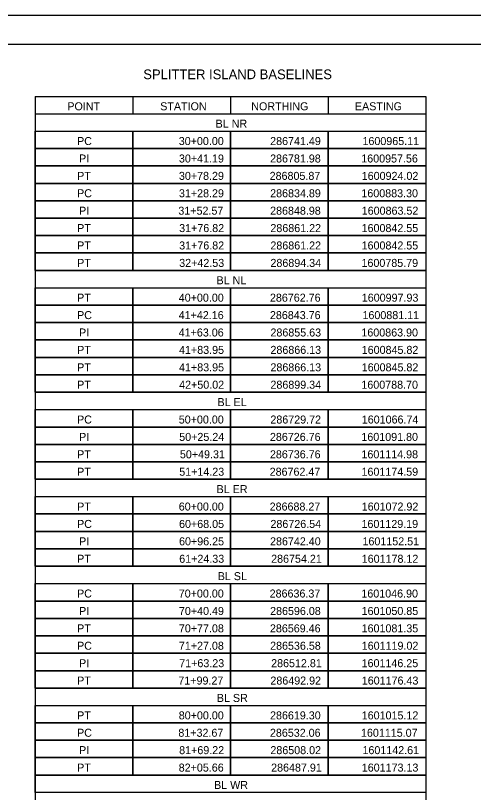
# Model space of a CAD drawing. Extents: x 0 to 34, y 0 to 22.
# Drawn here: x 17 to 25, y 8.41 to 22 of the extents above; entities that cross this region are included whole.
import ezdxf

# ---------------------------------------------------------------- set-up
doc = ezdxf.new("R2010")
doc.units = 0
for name, color, linetype in [('SH_Border', 7, 'Continuous'), ('SH_Cut_Line', 7, 'Continuous'), ('SH_Text', 7, 'Continuous')]:
    doc.layers.add(name, color=color, linetype=linetype)

msp = doc.modelspace()

# ---------------------------------------------------------------- linework, layer by layer
at = {"layer": 'SH_Border'}
msp.add_lwpolyline([(1.5, 21.5), (33.5, 21.5), (33.5, 0.5), (1.5, 0.5)], close=True, dxfattribs=at)
at = {"layer": 'SH_Cut_Line'}
msp.add_lwpolyline([(0, 0), (34, 0), (34, 22), (0, 22)], close=True, dxfattribs=at)
at = {"layer": 'SH_Text'}
for p, q in [((17.338, 20.587), (24.169, 20.587)), ((17.338, 20.587), (17.338, 19.674)), ((19.046, 20.587), (19.046, 20.283)), ((20.754, 20.587), (20.754, 20.283)), ((22.461, 20.587), (22.461, 20.283)), ((24.169, 20.587), (24.169, 19.674)), ((17.338, 20.283), (24.169, 20.283)), ((17.338, 19.978), (24.169, 19.978)), ((19.046, 19.978), (19.046, 19.674)), ((20.754, 19.978), (20.754, 19.674)), ((22.461, 19.978), (22.461, 19.674)), ((17.338, 19.674), (24.169, 19.674)), ((17.338, 19.674), (17.338, 19.37)), ((19.046, 19.674), (19.046, 19.37)), ((20.754, 19.674), (20.754, 19.37)), ((22.461, 19.674), (22.461, 19.37)), ((24.169, 19.674), (24.169, 19.37)), ((17.338, 19.37), (24.169, 19.37)), ((17.338, 19.37), (17.338, 18.761)), ((19.046, 19.37), (19.046, 18.761)), ((20.754, 19.37), (20.754, 18.761)), ((22.461, 19.37), (22.461, 18.761)), ((24.169, 19.37), (24.169, 18.761)), ((17.338, 19.065), (24.169, 19.065)), ((17.338, 18.761), (24.169, 18.761)), ((17.338, 18.761), (17.338, 18.457)), ((19.046, 18.761), (19.046, 18.457)), ((20.754, 18.761), (20.754, 18.457)), ((22.461, 18.761), (22.461, 18.457)), ((24.169, 18.761), (24.169, 18.457)), ((17.338, 18.457), (24.169, 18.457)), ((17.338, 18.457), (17.338, 16.63)), ((19.046, 18.457), (19.046, 17.543)), ((20.754, 18.457), (20.754, 17.543)), ((22.461, 18.457), (22.461, 17.543)), ((24.169, 18.457), (24.169, 16.63)), ((17.338, 18.152), (24.169, 18.152)), ((17.338, 17.848), (24.169, 17.848)), ((17.338, 17.543), (24.169, 17.543)), ((17.338, 17.239), (24.169, 17.239)), ((19.046, 17.239), (19.046, 16.63)), ((20.754, 17.239), (20.754, 16.63)), ((22.461, 17.239), (22.461, 16.63)), ((17.338, 16.935), (24.169, 16.935)), ((17.338, 16.63), (24.169, 16.63)), ((17.338, 16.63), (17.338, 16.326)), ((19.046, 16.63), (19.046, 16.326)), ((20.754, 16.63), (20.754, 16.326)), ((22.461, 16.63), (22.461, 16.326)), ((24.169, 16.63), (24.169, 16.326)), ((17.338, 16.326), (24.169, 16.326)), ((17.338, 16.326), (17.338, 14.804)), ((19.046, 16.326), (19.046, 15.413)), ((20.754, 16.326), (20.754, 15.413)), ((22.461, 16.326), (22.461, 15.413)), ((24.169, 16.326), (24.169, 14.804)), ((17.338, 16.022), (24.169, 16.022)), ((17.338, 15.717), (24.169, 15.717)), ((17.338, 15.413), (24.169, 15.413)), ((17.338, 15.109), (24.169, 15.109)), ((19.046, 15.109), (19.046, 14.804)), ((20.754, 15.109), (20.754, 14.804)), ((22.461, 15.109), (22.461, 14.804)), ((17.338, 14.804), (24.169, 14.804)), ((17.338, 14.804), (17.338, 14.5)), ((19.046, 14.804), (19.046, 14.5)), ((20.754, 14.804), (20.754, 14.5)), ((22.461, 14.804), (22.461, 14.5)), ((24.169, 14.804), (24.169, 14.5)), ((17.338, 14.5), (24.169, 14.5)), ((17.338, 14.5), (17.338, 12.978)), ((19.046, 14.5), (19.046, 13.891)), ((20.754, 14.5), (20.754, 13.891)), ((22.461, 14.5), (22.461, 13.891)), ((24.169, 14.5), (24.169, 12.978)), ((17.338, 14.196), (24.169, 14.196)), ((17.338, 13.891), (24.169, 13.891)), ((17.338, 13.587), (24.169, 13.587)), ((19.046, 13.587), (19.046, 12.978)), ((20.754, 13.587), (20.754, 12.978)), ((22.461, 13.587), (22.461, 12.978)), ((17.338, 13.283), (24.169, 13.283)), ((17.338, 12.978), (24.169, 12.978)), ((17.338, 12.978), (17.338, 12.674)), ((19.046, 12.978), (19.046, 12.674)), ((20.754, 12.978), (20.754, 12.674)), ((22.461, 12.978), (22.461, 12.674)), ((24.169, 12.978), (24.169, 12.674)), ((17.338, 12.674), (24.169, 12.674)), ((17.338, 12.674), (17.338, 11.761)), ((19.046, 12.674), (19.046, 12.37)), ((20.754, 12.674), (20.754, 12.37)), ((22.461, 12.674), (22.461, 12.37)), ((24.169, 12.674), (24.169, 11.761)), ((17.338, 12.37), (24.169, 12.37)), ((17.338, 12.065), (24.169, 12.065)), ((19.046, 12.065), (19.046, 11.761)), ((20.754, 12.065), (20.754, 11.761)), ((22.461, 12.065), (22.461, 11.761)), ((17.338, 11.761), (24.169, 11.761)), ((17.338, 11.761), (17.338, 11.457)), ((19.046, 11.761), (19.046, 11.457)), ((20.754, 11.761), (20.754, 11.457)), ((22.461, 11.761), (22.461, 11.457)), ((24.169, 11.761), (24.169, 11.457)), ((17.338, 11.457), (24.169, 11.457)), ((17.338, 11.457), (17.338, 10.848)), ((19.046, 11.457), (19.046, 10.848)), ((20.754, 11.457), (20.754, 10.848)), ((22.461, 11.457), (22.461, 10.848)), ((24.169, 11.457), (24.169, 10.848)), ((17.338, 11.152), (24.169, 11.152)), ((17.338, 10.848), (24.169, 10.848)), ((17.338, 10.848), (17.338, 10.543)), ((19.046, 10.848), (19.046, 10.543)), ((20.754, 10.848), (20.754, 10.543)), ((22.461, 10.848), (22.461, 10.543)), ((24.169, 10.848), (24.169, 10.543)), ((17.338, 10.543), (24.169, 10.543)), ((17.338, 10.543), (17.338, 9.326)), ((19.046, 10.543), (19.046, 10.239)), ((20.754, 10.543), (20.754, 10.239)), ((22.461, 10.543), (22.461, 10.239)), ((24.169, 10.543), (24.169, 9.326)), ((17.338, 10.239), (24.169, 10.239)), ((17.338, 9.935), (24.169, 9.935)), ((19.046, 9.935), (19.046, 9.326)), ((20.754, 9.935), (20.754, 9.326)), ((22.461, 9.935), (22.461, 9.326)), ((17.338, 9.63), (24.169, 9.63)), ((17.338, 9.326), (24.169, 9.326)), ((17.338, 9.326), (17.338, 9.022)), ((19.046, 9.326), (19.046, 9.022)), ((20.754, 9.326), (20.754, 9.022)), ((22.461, 9.326), (22.461, 9.022)), ((24.169, 9.326), (24.169, 9.022)), ((17.338, 9.022), (24.169, 9.022)), ((17.338, 9.022), (17.338, 8.109)), ((19.046, 9.022), (19.046, 8.717)), ((20.754, 9.022), (20.754, 8.717)), ((22.461, 9.022), (22.461, 8.717)), ((24.169, 9.022), (24.169, 8.109)), ((17.338, 8.717), (24.169, 8.717))]:
    msp.add_line(p, q, dxfattribs=at)
for points in [[(17.338, 19.978), (19.046, 19.978), (19.046, 19.674), (17.338, 19.674)], [(19.046, 19.978), (20.754, 19.978), (20.754, 19.674), (19.046, 19.674)], [(20.754, 19.978), (22.461, 19.978), (22.461, 19.674), (20.754, 19.674)], [(22.461, 19.978), (24.169, 19.978), (24.169, 19.674), (22.461, 19.674)], [(17.338, 19.674), (19.046, 19.674), (19.046, 19.37), (17.338, 19.37)], [(19.046, 19.674), (20.754, 19.674), (20.754, 19.37), (19.046, 19.37)], [(20.754, 19.674), (22.461, 19.674), (22.461, 19.37), (20.754, 19.37)], [(22.461, 19.674), (24.169, 19.674), (24.169, 19.37), (22.461, 19.37)], [(17.338, 19.37), (19.046, 19.37), (19.046, 19.065), (17.338, 19.065)], [(19.046, 19.37), (20.754, 19.37), (20.754, 19.065), (19.046, 19.065)], [(20.754, 19.37), (22.461, 19.37), (22.461, 19.065), (20.754, 19.065)], [(22.461, 19.37), (24.169, 19.37), (24.169, 19.065), (22.461, 19.065)], [(17.338, 19.065), (19.046, 19.065), (19.046, 18.761), (17.338, 18.761)], [(19.046, 19.065), (20.754, 19.065), (20.754, 18.761), (19.046, 18.761)], [(20.754, 19.065), (22.461, 19.065), (22.461, 18.761), (20.754, 18.761)], [(22.461, 19.065), (24.169, 19.065), (24.169, 18.761), (22.461, 18.761)], [(17.338, 18.761), (19.046, 18.761), (19.046, 18.457), (17.338, 18.457)], [(19.046, 18.761), (20.754, 18.761), (20.754, 18.457), (19.046, 18.457)], [(20.754, 18.761), (22.461, 18.761), (22.461, 18.457), (20.754, 18.457)], [(22.461, 18.761), (24.169, 18.761), (24.169, 18.457), (22.461, 18.457)], [(17.338, 18.457), (19.046, 18.457), (19.046, 18.152), (17.338, 18.152)], [(19.046, 18.457), (20.754, 18.457), (20.754, 18.152), (19.046, 18.152)], [(20.754, 18.457), (22.461, 18.457), (22.461, 18.152), (20.754, 18.152)], [(22.461, 18.457), (24.169, 18.457), (24.169, 18.152), (22.461, 18.152)], [(17.338, 18.152), (19.046, 18.152), (19.046, 17.848), (17.338, 17.848)], [(19.046, 18.152), (20.754, 18.152), (20.754, 17.848), (19.046, 17.848)], [(20.754, 18.152), (22.461, 18.152), (22.461, 17.848), (20.754, 17.848)], [(22.461, 18.152), (24.169, 18.152), (24.169, 17.848), (22.461, 17.848)], [(17.338, 17.848), (19.046, 17.848), (19.046, 17.543), (17.338, 17.543)], [(19.046, 17.848), (20.754, 17.848), (20.754, 17.543), (19.046, 17.543)], [(20.754, 17.848), (22.461, 17.848), (22.461, 17.543), (20.754, 17.543)], [(22.461, 17.848), (24.169, 17.848), (24.169, 17.543), (22.461, 17.543)], [(17.338, 17.239), (19.046, 17.239), (19.046, 16.935), (17.338, 16.935)], [(19.046, 17.239), (20.754, 17.239), (20.754, 16.935), (19.046, 16.935)], [(20.754, 17.239), (22.461, 17.239), (22.461, 16.935), (20.754, 16.935)], [(22.461, 17.239), (24.169, 17.239), (24.169, 16.935), (22.461, 16.935)], [(17.338, 16.935), (19.046, 16.935), (19.046, 16.63), (17.338, 16.63)], [(19.046, 16.935), (20.754, 16.935), (20.754, 16.63), (19.046, 16.63)], [(20.754, 16.935), (22.461, 16.935), (22.461, 16.63), (20.754, 16.63)], [(22.461, 16.935), (24.169, 16.935), (24.169, 16.63), (22.461, 16.63)], [(17.338, 16.63), (19.046, 16.63), (19.046, 16.326), (17.338, 16.326)], [(19.046, 16.63), (20.754, 16.63), (20.754, 16.326), (19.046, 16.326)], [(20.754, 16.63), (22.461, 16.63), (22.461, 16.326), (20.754, 16.326)], [(22.461, 16.63), (24.169, 16.63), (24.169, 16.326), (22.461, 16.326)], [(17.338, 16.326), (19.046, 16.326), (19.046, 16.022), (17.338, 16.022)], [(19.046, 16.326), (20.754, 16.326), (20.754, 16.022), (19.046, 16.022)], [(20.754, 16.326), (22.461, 16.326), (22.461, 16.022), (20.754, 16.022)], [(22.461, 16.326), (24.169, 16.326), (24.169, 16.022), (22.461, 16.022)], [(17.338, 16.022), (19.046, 16.022), (19.046, 15.717), (17.338, 15.717)], [(19.046, 16.022), (20.754, 16.022), (20.754, 15.717), (19.046, 15.717)], [(20.754, 16.022), (22.461, 16.022), (22.461, 15.717), (20.754, 15.717)], [(22.461, 16.022), (24.169, 16.022), (24.169, 15.717), (22.461, 15.717)], [(17.338, 15.717), (19.046, 15.717), (19.046, 15.413), (17.338, 15.413)], [(19.046, 15.717), (20.754, 15.717), (20.754, 15.413), (19.046, 15.413)], [(20.754, 15.717), (22.461, 15.717), (22.461, 15.413), (20.754, 15.413)], [(22.461, 15.717), (24.169, 15.717), (24.169, 15.413), (22.461, 15.413)], [(17.338, 15.109), (19.046, 15.109), (19.046, 14.804), (17.338, 14.804)], [(19.046, 15.109), (20.754, 15.109), (20.754, 14.804), (19.046, 14.804)], [(20.754, 15.109), (22.461, 15.109), (22.461, 14.804), (20.754, 14.804)], [(22.461, 15.109), (24.169, 15.109), (24.169, 14.804), (22.461, 14.804)], [(17.338, 14.804), (19.046, 14.804), (19.046, 14.5), (17.338, 14.5)], [(19.046, 14.804), (20.754, 14.804), (20.754, 14.5), (19.046, 14.5)], [(20.754, 14.804), (22.461, 14.804), (22.461, 14.5), (20.754, 14.5)], [(22.461, 14.804), (24.169, 14.804), (24.169, 14.5), (22.461, 14.5)], [(17.338, 14.5), (19.046, 14.5), (19.046, 14.196), (17.338, 14.196)], [(19.046, 14.5), (20.754, 14.5), (20.754, 14.196), (19.046, 14.196)], [(20.754, 14.5), (22.461, 14.5), (22.461, 14.196), (20.754, 14.196)], [(22.461, 14.5), (24.169, 14.5), (24.169, 14.196), (22.461, 14.196)], [(17.338, 14.196), (19.046, 14.196), (19.046, 13.891), (17.338, 13.891)], [(19.046, 14.196), (20.754, 14.196), (20.754, 13.891), (19.046, 13.891)], [(20.754, 14.196), (22.461, 14.196), (22.461, 13.891), (20.754, 13.891)], [(22.461, 14.196), (24.169, 14.196), (24.169, 13.891), (22.461, 13.891)], [(17.338, 13.587), (19.046, 13.587), (19.046, 13.283), (17.338, 13.283)], [(19.046, 13.587), (20.754, 13.587), (20.754, 13.283), (19.046, 13.283)], [(20.754, 13.587), (22.461, 13.587), (22.461, 13.283), (20.754, 13.283)], [(22.461, 13.587), (24.169, 13.587), (24.169, 13.283), (22.461, 13.283)], [(17.338, 13.283), (19.046, 13.283), (19.046, 12.978), (17.338, 12.978)], [(19.046, 13.283), (20.754, 13.283), (20.754, 12.978), (19.046, 12.978)], [(20.754, 13.283), (22.461, 13.283), (22.461, 12.978), (20.754, 12.978)], [(22.461, 13.283), (24.169, 13.283), (24.169, 12.978), (22.461, 12.978)], [(17.338, 12.978), (19.046, 12.978), (19.046, 12.674), (17.338, 12.674)], [(19.046, 12.978), (20.754, 12.978), (20.754, 12.674), (19.046, 12.674)], [(20.754, 12.978), (22.461, 12.978), (22.461, 12.674), (20.754, 12.674)], [(22.461, 12.978), (24.169, 12.978), (24.169, 12.674), (22.461, 12.674)], [(17.338, 12.674), (19.046, 12.674), (19.046, 12.37), (17.338, 12.37)], [(19.046, 12.674), (20.754, 12.674), (20.754, 12.37), (19.046, 12.37)], [(20.754, 12.674), (22.461, 12.674), (22.461, 12.37), (20.754, 12.37)], [(22.461, 12.674), (24.169, 12.674), (24.169, 12.37), (22.461, 12.37)], [(17.338, 12.065), (19.046, 12.065), (19.046, 11.761), (17.338, 11.761)], [(19.046, 12.065), (20.754, 12.065), (20.754, 11.761), (19.046, 11.761)], [(20.754, 12.065), (22.461, 12.065), (22.461, 11.761), (20.754, 11.761)], [(22.461, 12.065), (24.169, 12.065), (24.169, 11.761), (22.461, 11.761)], [(17.338, 11.761), (19.046, 11.761), (19.046, 11.457), (17.338, 11.457)], [(19.046, 11.761), (20.754, 11.761), (20.754, 11.457), (19.046, 11.457)], [(20.754, 11.761), (22.461, 11.761), (22.461, 11.457), (20.754, 11.457)], [(22.461, 11.761), (24.169, 11.761), (24.169, 11.457), (22.461, 11.457)], [(17.338, 11.457), (19.046, 11.457), (19.046, 11.152), (17.338, 11.152)], [(19.046, 11.457), (20.754, 11.457), (20.754, 11.152), (19.046, 11.152)], [(20.754, 11.457), (22.461, 11.457), (22.461, 11.152), (20.754, 11.152)], [(22.461, 11.457), (24.169, 11.457), (24.169, 11.152), (22.461, 11.152)], [(17.338, 11.152), (19.046, 11.152), (19.046, 10.848), (17.338, 10.848)], [(19.046, 11.152), (20.754, 11.152), (20.754, 10.848), (19.046, 10.848)], [(20.754, 11.152), (22.461, 11.152), (22.461, 10.848), (20.754, 10.848)], [(22.461, 11.152), (24.169, 11.152), (24.169, 10.848), (22.461, 10.848)], [(17.338, 10.848), (19.046, 10.848), (19.046, 10.543), (17.338, 10.543)], [(19.046, 10.848), (20.754, 10.848), (20.754, 10.543), (19.046, 10.543)], [(20.754, 10.848), (22.461, 10.848), (22.461, 10.543), (20.754, 10.543)], [(22.461, 10.848), (24.169, 10.848), (24.169, 10.543), (22.461, 10.543)], [(17.338, 10.543), (19.046, 10.543), (19.046, 10.239), (17.338, 10.239)], [(19.046, 10.543), (20.754, 10.543), (20.754, 10.239), (19.046, 10.239)], [(20.754, 10.543), (22.461, 10.543), (22.461, 10.239), (20.754, 10.239)], [(22.461, 10.543), (24.169, 10.543), (24.169, 10.239), (22.461, 10.239)], [(17.338, 9.935), (19.046, 9.935), (19.046, 9.63), (17.338, 9.63)], [(19.046, 9.935), (20.754, 9.935), (20.754, 9.63), (19.046, 9.63)], [(20.754, 9.935), (22.461, 9.935), (22.461, 9.63), (20.754, 9.63)], [(22.461, 9.935), (24.169, 9.935), (24.169, 9.63), (22.461, 9.63)], [(17.338, 9.63), (19.046, 9.63), (19.046, 9.326), (17.338, 9.326)], [(19.046, 9.63), (20.754, 9.63), (20.754, 9.326), (19.046, 9.326)], [(20.754, 9.63), (22.461, 9.63), (22.461, 9.326), (20.754, 9.326)], [(22.461, 9.63), (24.169, 9.63), (24.169, 9.326), (22.461, 9.326)], [(17.338, 9.326), (19.046, 9.326), (19.046, 9.022), (17.338, 9.022)], [(19.046, 9.326), (20.754, 9.326), (20.754, 9.022), (19.046, 9.022)], [(20.754, 9.326), (22.461, 9.326), (22.461, 9.022), (20.754, 9.022)], [(22.461, 9.326), (24.169, 9.326), (24.169, 9.022), (22.461, 9.022)], [(17.338, 9.022), (19.046, 9.022), (19.046, 8.717), (17.338, 8.717)], [(19.046, 9.022), (20.754, 9.022), (20.754, 8.717), (19.046, 8.717)], [(20.754, 9.022), (22.461, 9.022), (22.461, 8.717), (20.754, 8.717)], [(22.461, 9.022), (24.169, 9.022), (24.169, 8.717), (22.461, 8.717)], [(17.338, 8.717), (24.169, 8.717), (24.169, 8.413), (17.338, 8.413)]]:
    msp.add_lwpolyline(points, close=True, dxfattribs=at)

# ---------------------------------------------------------------- texts
for s, height, p in [('SPLITTER ISLAND BASELINES', 0.17, (19.23, 20.887)), ('POINT', 0.14, (17.903, 20.343)), ('STATION', 0.14, (19.526, 20.343)), ('NORTHING', 0.14, (21.117, 20.343)), ('EASTING', 0.14, (22.928, 20.343)), ('BL NR', 0.14, (20.494, 20.039)), ('PC', 0.14, (18.073, 19.735)), ('30+00.00', 0.14, (19.85, 19.735)), ('286741.49', 0.14, (21.447, 19.735)), ('1600965.11', 0.14, (23.06, 19.735)), ('PI', 0.14, (18.108, 19.43)), ('30+41.19', 0.14, (19.853, 19.43)), ('286781.98', 0.14, (21.446, 19.43)), ('1600957.56', 0.14, (23.039, 19.43)), ('PT', 0.14, (18.074, 19.126)), ('30+78.29', 0.14, (19.853, 19.126)), ('286805.87', 0.14, (21.438, 19.126)), ('1600924.02', 0.14, (23.047, 19.126)), ('PC', 0.14, (18.073, 18.822)), ('31+28.29', 0.14, (19.853, 18.822)), ('286834.89', 0.14, (21.447, 18.822)), ('1600883.30', 0.14, (23.041, 18.822)), ('PI', 0.14, (18.108, 18.517)), ('31+52.57', 0.14, (19.843, 18.517)), ('286848.98', 0.14, (21.446, 18.517)), ('1600863.52', 0.14, (23.047, 18.517)), ('PT', 0.14, (18.074, 18.213)), ('31+76.82', 0.14, (19.857, 18.213)), ('286861.22', 0.14, (21.451, 18.213)), ('1600842.55', 0.14, (23.045, 18.213)), ('PT', 0.14, (18.074, 17.909)), ('31+76.82', 0.14, (19.857, 17.909)), ('286861.22', 0.14, (21.451, 17.909)), ('1600842.55', 0.14, (23.045, 17.909)), ('PT', 0.14, (18.074, 17.604)), ('32+42.53', 0.14, (19.858, 17.604)), ('286894.34', 0.14, (21.452, 17.604)), ('1600785.79', 0.14, (23.043, 17.604)), ('BL NL', 0.14, (20.51, 17.3)), ('PT', 0.14, (18.074, 16.996)), ('40+00.00', 0.14, (19.85, 16.996)), ('286762.76', 0.14, (21.443, 16.996)), ('1600997.93', 0.14, (23.048, 16.996)), ('PC', 0.14, (18.073, 16.691)), ('41+42.16', 0.14, (19.849, 16.691)), ('286843.76', 0.14, (21.443, 16.691)), ('1600881.11', 0.14, (23.06, 16.691)), ('PI', 0.14, (18.108, 16.387)), ('41+63.06', 0.14, (19.849, 16.387)), ('286855.63', 0.14, (21.452, 16.387)), ('1600863.90', 0.14, (23.041, 16.387)), ('PT', 0.14, (18.074, 16.083)), ('41+83.95', 0.14, (19.855, 16.083)), ('286866.13', 0.14, (21.452, 16.083)), ('1600845.82', 0.14, (23.047, 16.083)), ('PT', 0.14, (18.074, 15.778)), ('41+83.95', 0.14, (19.855, 15.778)), ('286866.13', 0.14, (21.452, 15.778)), ('1600845.82', 0.14, (23.047, 15.778)), ('PT', 0.14, (18.074, 15.474)), ('42+50.02', 0.14, (19.857, 15.474)), ('286899.34', 0.14, (21.452, 15.474)), ('1600788.70', 0.14, (23.041, 15.474)), ('BL EL', 0.14, (20.527, 15.17)), ('PC', 0.14, (18.073, 14.865)), ('50+00.00', 0.14, (19.85, 14.865)), ('286729.72', 0.14, (21.451, 14.865)), ('1601066.74', 0.14, (23.048, 14.865)), ('PI', 0.14, (18.108, 14.561)), ('50+25.24', 0.14, (19.858, 14.561)), ('286726.76', 0.14, (21.443, 14.561)), ('1601091.80', 0.14, (23.041, 14.561)), ('PT', 0.14, (18.074, 14.257)), ('50+49.31', 0.14, (19.87, 14.257)), ('286736.76', 0.14, (21.443, 14.257)), ('1601114.98', 0.14, (23.042, 14.257)), ('PT', 0.14, (18.074, 13.952)), ('51+14.23', 0.14, (19.858, 13.952)), ('286762.47', 0.14, (21.438, 13.952)), ('1601174.59', 0.14, (23.043, 13.952)), ('BL ER', 0.14, (20.511, 13.648)), ('PT', 0.14, (18.074, 13.343)), ('60+00.00', 0.14, (19.85, 13.343)), ('286688.27', 0.14, (21.438, 13.343)), ('1601072.92', 0.14, (23.047, 13.343)), ('PC', 0.14, (18.073, 13.039)), ('60+68.05', 0.14, (19.855, 13.039)), ('286726.54', 0.14, (21.452, 13.039)), ('1601129.19', 0.14, (23.043, 13.039)), ('PI', 0.14, (18.108, 12.735)), ('60+96.25', 0.14, (19.855, 12.735)), ('286742.40', 0.14, (21.445, 12.735)), ('1601152.51', 0.14, (23.06, 12.735)), ('PT', 0.14, (18.074, 12.43)), ('61+24.33', 0.14, (19.858, 12.43)), ('286754.21', 0.14, (21.464, 12.43)), ('1601178.12', 0.14, (23.047, 12.43)), ('BL SL', 0.14, (20.531, 12.126)), ('PC', 0.14, (18.073, 11.822)), ('70+00.00', 0.14, (19.85, 11.822)), ('286636.37', 0.14, (21.438, 11.822)), ('1601046.90', 0.14, (23.041, 11.822)), ('PI', 0.14, (18.108, 11.517)), ('70+40.49', 0.14, (19.853, 11.517)), ('286596.08', 0.14, (21.446, 11.517)), ('1601050.85', 0.14, (23.045, 11.517)), ('PT', 0.14, (18.074, 11.213)), ('70+77.08', 0.14, (19.852, 11.213)), ('286569.46', 0.14, (21.443, 11.213)), ('1601081.35', 0.14, (23.045, 11.213)), ('PC', 0.14, (18.073, 10.909)), ('71+27.08', 0.14, (19.852, 10.909)), ('286536.58', 0.14, (21.446, 10.909)), ('1601119.02', 0.14, (23.047, 10.909)), ('PI', 0.14, (18.108, 10.604)), ('71+63.23', 0.14, (19.858, 10.604)), ('286512.81', 0.14, (21.464, 10.604)), ('1601146.25', 0.14, (23.045, 10.604)), ('PT', 0.14, (18.074, 10.3)), ('71+99.27', 0.14, (19.843, 10.3)), ('286492.92', 0.14, (21.451, 10.3)), ('1601176.43', 0.14, (23.048, 10.3)), ('BL SR', 0.14, (20.515, 9.996)), ('PT', 0.14, (18.074, 9.691)), ('80+00.00', 0.14, (19.85, 9.691)), ('286619.30', 0.14, (21.445, 9.691)), ('1601015.12', 0.14, (23.047, 9.691)), ('PC', 0.14, (18.073, 9.387)), ('81+32.67', 0.14, (19.843, 9.387)), ('286532.06', 0.14, (21.443, 9.387)), ('1601115.07', 0.14, (23.034, 9.387)), ('PI', 0.14, (18.108, 9.083)), ('81+69.22', 0.14, (19.857, 9.083)), ('286508.02', 0.14, (21.451, 9.083)), ('1601142.61', 0.14, (23.06, 9.083)), ('PT', 0.14, (18.074, 8.778)), ('82+05.66', 0.14, (19.849, 8.778)), ('286487.91', 0.14, (21.464, 8.778)), ('1601173.13', 0.14, (23.048, 8.778)), ('BL WR', 0.14, (20.467, 8.474))]:
    msp.add_text(s, height=height, dxfattribs=at).set_placement(p)

doc.saveas('drawing.dxf')
